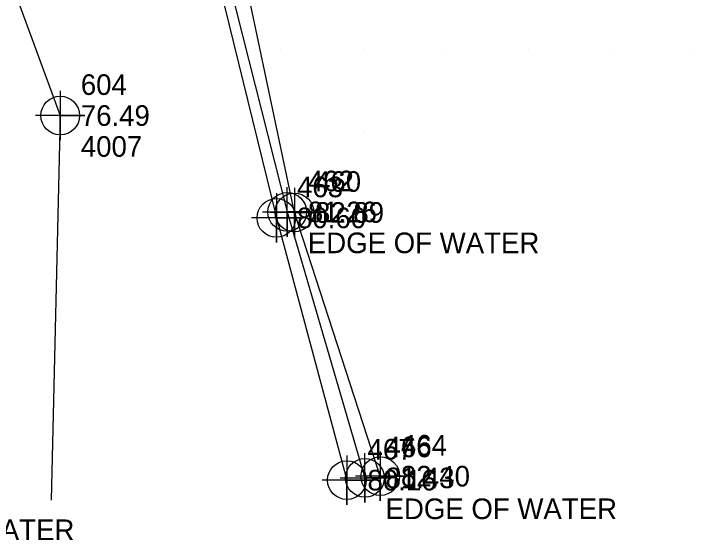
# Model space of a CAD drawing. Extents: x 1988140 to 1988766, y 249950 to 250250.
# Drawn here: x 1988457.6 to 1988540, y 249950.5 to 250014.3 of the extents above; entities that cross this region are included whole.
import ezdxf

# ---------------------------------------------------------------- set-up
doc = ezdxf.new("R2010")
doc.units = 0
for name, color, linetype in [('Exist DTM Breakline', 7, 'Continuous'), ('Exist DTM Breakline Cogo Elevation', 7, 'Continuous'), ('Exist DTM Breakline Cogo Number', 7, 'Continuous'), ('Exist DTM Breakline Cogo Point CELL', 7, 'Continuous'), ('Exist DTM Breakline Underwater', 7, 'Continuous'), ('Exist DTM Breakline Underwater Cogo Comment', 7, 'Continuous'), ('Exist DTM Breakline Underwater Cogo Elevation', 7, 'Continuous'), ('Exist DTM Breakline Underwater Cogo Number', 7, 'Continuous'), ('Exist DTM Breakline Underwater Cogo Point CELL', 7, 'Continuous'), ('Exist DTM QL2 LIDAR Elevation Point', 7, 'Continuous'), ('Exist Hydro Stream or Body of Water', 7, 'Continuous'), ('Exist Hydro Stream or Body of Water Cogo Comment', 7, 'Continuous'), ('Exist Hydro Stream or Body of Water Cogo Elevation', 7, 'Continuous'), ('Exist Hydro Stream or Body of Water Cogo Number', 7, 'Continuous'), ('Exist Hydro Stream or Body of Water Cogo Point CELL', 7, 'Continuous')]:
    doc.layers.add(name, color=color, linetype=linetype)

msp = doc.modelspace()

# ---------------------------------------------------------------- linework, layer by layer
at = {"layer": 'Exist DTM Breakline'}
msp.add_lwpolyline([(1988502.0577, 249958.2531), (1988491.6502, 249990.2233), (1988485.1148, 250021.3111), (1988477.2086, 250042.1909), (1988478.2961, 250054.8431), (1988462.5221, 250084.1865), (1988467.6761, 250104.4545), (1988466.937, 250133.0471)], dxfattribs=at)
at = {"layer": 'Exist DTM Breakline Cogo Point CELL'}
for points in [[(1988489.4621, 249992.5681), (1988489.4621, 249986.5681), (1988489.4621, 249989.5681), (1988492.4621, 249989.5681), (1988486.4621, 249989.5681)], [(1988491.6502, 249993.2233), (1988491.6502, 249987.2233), (1988491.6502, 249990.2233), (1988494.6502, 249990.2233), (1988488.6502, 249990.2233)], [(1988502.0577, 249961.2531), (1988502.0577, 249955.2531), (1988502.0577, 249958.2531), (1988505.0577, 249958.2531), (1988499.0577, 249958.2531)], [(1988498.0052, 249960.771), (1988498.0052, 249954.771), (1988498.0052, 249957.771), (1988501.0052, 249957.771), (1988495.0052, 249957.771)]]:
    msp.add_lwpolyline(points, dxfattribs=at)
for centre in [(1988491.6502, 249990.2233), (1988489.4621, 249989.5681), (1988502.0577, 249958.2531), (1988498.0052, 249957.771)]:
    msp.add_circle(centre, 2.344, dxfattribs=at)
at = {"layer": 'Exist DTM Breakline Underwater'}
for points in [[(1988432.5434, 250186.7094), (1988425.7037, 250133.7144), (1988438.98, 250078.1677), (1988446.627, 250047.162), (1988463.2661, 250001.9742), (1988462.1612, 249955.3502)], [(1988472.6196, 250042.0736), (1988481.9819, 250020.1998), (1988489.4621, 249989.5681), (1988498.0052, 249957.771)]]:
    msp.add_lwpolyline(points, dxfattribs=at)
at = {"layer": 'Exist DTM Breakline Underwater Cogo Point CELL'}
msp.add_lwpolyline([(1988463.2661, 250004.9742), (1988463.2661, 249998.9742), (1988463.2661, 250001.9742), (1988466.2661, 250001.9742), (1988460.2661, 250001.9742)], dxfattribs=at)
msp.add_circle((1988463.2661, 250001.9742), 2.344, dxfattribs=at)
at = {"layer": 'Exist DTM QL2 LIDAR Elevation Point'}
for p, q in [((1988490, 250010), (1988490, 250010)), ((1988500, 250010), (1988500, 250010)), ((1988510, 250010), (1988510, 250010)), ((1988520, 250010), (1988520, 250010)), ((1988530, 250010), (1988530, 250010)), ((1988540, 250010), (1988540, 250010)), ((1988490, 250000), (1988490, 250000)), ((1988500, 250000), (1988500, 250000))]:
    msp.add_line(p, q, dxfattribs=at)
at = {"layer": 'Exist Hydro Stream or Body of Water'}
msp.add_lwpolyline([(1988474.7634, 250042.2609), (1988483.0043, 250020.9618), (1988490.779, 249990.2887), (1988500.1927, 249958.0481)], dxfattribs=at)
at = {"layer": 'Exist Hydro Stream or Body of Water Cogo Point CELL'}
for points in [[(1988487.779, 249990.2887), (1988493.779, 249990.2887), (1988490.779, 249990.2887), (1988490.779, 249987.2887), (1988490.779, 249993.2887)], [(1988497.1927, 249958.0481), (1988503.1927, 249958.0481), (1988500.1927, 249958.0481), (1988500.1927, 249955.0481), (1988500.1927, 249961.0481)]]:
    msp.add_lwpolyline(points, dxfattribs=at)
for centre in [(1988490.779, 249990.2887), (1988500.1927, 249958.0481)]:
    msp.add_circle(centre, 2.344, dxfattribs=at)

# ---------------------------------------------------------------- texts
at = {"layer": 'Exist DTM Breakline Cogo Elevation'}
for s, p in [('80.60', (1988491.9621, 249988.3181)), ('82.89', (1988494.1502, 249988.9733)), ('82.40', (1988504.5577, 249957.0031)), ('80.16', (1988500.5052, 249956.521))]:
    msp.add_text(s, height=2.5, dxfattribs=at).set_placement(p)
at = {"layer": 'Exist DTM Breakline Cogo Number'}
for s, p in [('460', (1988494.1502, 249992.7233)), ('463', (1988491.9621, 249992.0681)), ('467', (1988500.5052, 249960.271)), ('464', (1988504.5577, 249960.7531))]:
    msp.add_text(s, height=2.5, dxfattribs=at).set_placement(p)
at = {"layer": 'Exist DTM Breakline Underwater Cogo Comment'}
msp.add_text('4007', height=2.5, dxfattribs=at).set_placement((1988465.7661, 249996.9742))
at = {"layer": 'Exist DTM Breakline Underwater Cogo Elevation'}
msp.add_text('76.49', height=2.5, dxfattribs=at).set_placement((1988465.7661, 250000.7242))
at = {"layer": 'Exist DTM Breakline Underwater Cogo Number'}
msp.add_text('604', height=2.5, dxfattribs=at).set_placement((1988465.7661, 250004.4742))
at = {"layer": 'Exist Hydro Stream or Body of Water Cogo Comment'}
for p in [(1988493.279, 249985.2887), (1988502.6927, 249953.0481), (1988436.9391, 249950.5004)]:
    msp.add_text('EDGE OF WATER', height=2.5, dxfattribs=at).set_placement(p)
at = {"layer": 'Exist Hydro Stream or Body of Water Cogo Elevation'}
for s, p in [('81.26', (1988493.279, 249989.0387)), ('81.43', (1988502.6927, 249956.7981))]:
    msp.add_text(s, height=2.5, dxfattribs=at).set_placement(p)
at = {"layer": 'Exist Hydro Stream or Body of Water Cogo Number'}
for s, p in [('462', (1988493.279, 249992.7887)), ('466', (1988502.6927, 249960.5481))]:
    msp.add_text(s, height=2.5, dxfattribs=at).set_placement(p)

doc.saveas('drawing.dxf')
